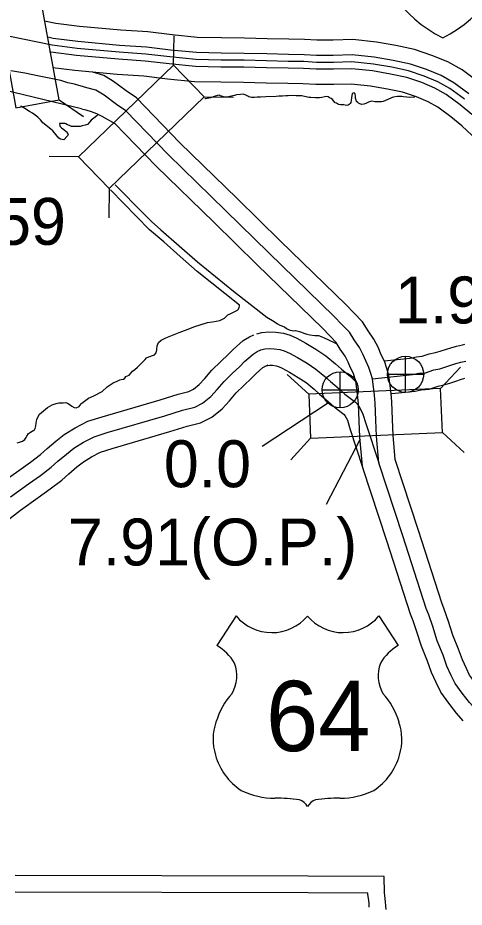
# Model space of a CAD drawing. Extents: x -83719 to 153526, y -11835 to 11446.
# Drawn here: x -2255.2 to -2121.1, y 1185.3 to 1452.3 of the extents above; entities that cross this region are included whole.
import ezdxf

# ---------------------------------------------------------------- set-up
doc = ezdxf.new("R2010")
doc.units = 0
for name, color, linetype in [('Level 10', 7, 'Continuous'), ('Level 15', 7, 'Continuous'), ('Level 19', 7, 'Continuous'), ('Level 20', 7, 'Continuous'), ('Level 22', 7, 'Continuous'), ('Level 23', 7, 'Continuous'), ('Level 25', 7, 'Continuous'), ('Level 26', 7, 'Continuous'), ('Level 58', 7, 'Continuous'), ('Level 59', 7, 'Continuous'), ('Level 9', 7, 'Continuous')]:
    doc.layers.add(name, color=color, linetype=linetype)

msp = doc.modelspace()

# ---------------------------------------------------------------- linework, layer by layer
at = {"layer": 'Level 10'}
for points in [[(-2260.36, 1312.57), (-2254.83, 1316.47), (-2251.37, 1318.93), (-2248.36, 1321.25), (-2246.38, 1323.01), (-2243.74, 1325.25), (-2241.2, 1327.26), (-2237.91, 1329.27), (-2234.14, 1331.2), (-2229.78, 1332.57), (-2212.46, 1337.66), (-2207.05, 1339.38), (-2203.77, 1340.18), (-2202.41, 1340.86), (-2200.68, 1342.29), (-2199.05, 1344.03), (-2196.88, 1346.6), (-2194.25, 1349.13), (-2192.05, 1351.21), (-2190.55, 1352.77), (-2187.46, 1355.48), (-2185.61, 1356.55), (-2184.34, 1357.15)], [(-2183.39, 1357.49), (-2181.85, 1357.87), (-2179.78, 1358.05), (-2177.73, 1357.99), (-2175.36, 1357.61), (-2173.42, 1357.01), (-2171.42, 1356.13), (-2168.7, 1354.66), (-2165.64, 1352.85), (-2162.68, 1350.85), (-2159.74, 1348.48), (-2157.98, 1346.9), (-2155.29, 1344.63), (-2153.74, 1343.15), (-2153.72, 1343.14)], [(-2145.14, 1349.35), (-2137.37, 1350.18), (-2135.46, 1350.55), (-2133.79, 1350.72), (-2131.61, 1351.44), (-2129.71, 1351.85), (-2128.4, 1352.23), (-2126.43, 1352.89), (-2125.11, 1353.3), (-2123.42, 1353.78), (-2121.67, 1354.19), (-2120.91, 1354.34)], [(-2258.87, 1301.02), (-2254.38, 1304.55), (-2249.05, 1308.3), (-2245.41, 1310.9), (-2241.97, 1313.55), (-2239.82, 1315.46), (-2237.4, 1317.51), (-2235.47, 1319.04), (-2233.02, 1320.54), (-2230.33, 1321.91), (-2226.87, 1323), (-2209.53, 1328.09), (-2204.34, 1329.75), (-2200.33, 1330.73), (-2196.94, 1332.41), (-2193.81, 1334.99), (-2191.57, 1337.38), (-2189.57, 1339.76), (-2187.34, 1341.9), (-2185.02, 1344.1), (-2183.64, 1345.53), (-2181.61, 1347.31), (-2180.96, 1347.68), (-2180.04, 1348.12)], [(-2181, 1347.78), (-2180.21, 1347.97), (-2179.49, 1348.04), (-2178.68, 1348.01), (-2177.64, 1347.84), (-2176.91, 1347.62), (-2175.82, 1347.14), (-2173.63, 1345.96), (-2170.98, 1344.39), (-2168.63, 1342.81), (-2166.23, 1340.86), (-2164.54, 1339.36), (-2161.97, 1337.18), (-2160.21, 1335.51), (-2157.19, 1333.23), (-2156.95, 1332.97), (-2156.22, 1331.5), (-2155.47, 1328.99), (-2151.53, 1317.16)], [(-2142.87, 1339.53), (-2135.89, 1340.28), (-2134.02, 1340.65), (-2131.7, 1340.88), (-2128.98, 1341.78), (-2127.23, 1342.16), (-2125.42, 1342.69), (-2123.36, 1343.37), (-2122.23, 1343.73), (-2120.93, 1344.1)], [(-2144.54, 1184.64), (-2144.67, 1185.72), (-2144.72, 1186.96), (-2144.96, 1188.82), (-2145.09, 1189.59), (-2145.17, 1194.54), (-2167.98, 1194.68), (-2255.99, 1194.88)]]:
    msp.add_lwpolyline(points, dxfattribs=at)
at = {"layer": 'Level 15'}
for points in [[(-2236.07, 1425.02), (-2409.06, 1466.86)], [(-2229.34, 1435.04), (-2232.67, 1435.99)], [(-2143.78, 1344.93), (-2144.37, 1347.02), (-2145.1, 1349.25), (-2146.12, 1351.4), (-2146.92, 1353.27), (-2148.28, 1355.9), (-2150, 1358.37), (-2151.64, 1361.02), (-2154.27, 1363.77), (-2156.61, 1366.2), (-2176.31, 1385.31), (-2189.27, 1398.08), (-2206.51, 1414.84), (-2219.51, 1428.3), (-2222.58, 1430.39), (-2226.41, 1433.23), (-2229.34, 1435.04)], [(-2236.07, 1425.02), (-2234.78, 1424.66), (-2233.1, 1424.19), (-2231.49, 1423.59), (-2229.88, 1422.79), (-2225.99, 1420.61)], [(-2153.5, 1342.58), (-2153.94, 1344.11), (-2154.4, 1345.53), (-2155.24, 1347.29), (-2155.97, 1349), (-2156.87, 1350.73), (-2158.36, 1352.88), (-2159.58, 1354.86), (-2161.49, 1356.84), (-2163.7, 1359.14), (-2183.3, 1378.16), (-2196.26, 1390.94), (-2213.59, 1407.78), (-2225.99, 1420.61)], [(-2151.72, 1317.73), (-2152.44, 1326.42), (-2152.65, 1331.32), (-2152.87, 1336.35), (-2153.05, 1338.48), (-2153.65, 1343.32)], [(-2141.85, 1319.74), (-2142.46, 1327.05), (-2142.66, 1331.75), (-2142.88, 1337), (-2143.11, 1339.53), (-2143.78, 1344.93)], [(-2113.97, 1247.95), (-2115.75, 1249.95), (-2117.78, 1252.6), (-2119.56, 1255.03), (-2120.5, 1256.98), (-2121.67, 1259.55), (-2122.83, 1262.79), (-2124.58, 1267.01), (-2125.81, 1271.12), (-2127.11, 1274.84), (-2127.88, 1276.73), (-2134.84, 1298.38), (-2141.85, 1319.74)], [(-2121.44, 1241.31), (-2123.46, 1243.58), (-2125.78, 1246.6), (-2128.16, 1249.85), (-2129.56, 1252.73), (-2130.95, 1255.79), (-2132.16, 1259.19), (-2134.01, 1263.65), (-2135.32, 1268.04), (-2136.46, 1271.29), (-2137.29, 1273.31), (-2144.35, 1295.29), (-2151.53, 1317.18)]]:
    msp.add_lwpolyline(points, dxfattribs=at)
at = {"layer": 'Level 19'}
for points in [[(-2116.98, 1433.15), (-2121.78, 1436.68), (-2126.09, 1439.13), (-2130.83, 1441.07), (-2136.08, 1442.85), (-2141.64, 1444.05), (-2147.5, 1445.06), (-2154.6, 1445.79), (-2160.49, 1445.62), (-2165.34, 1445.64), (-2169.05, 1445.84), (-2173.83, 1445.93), (-2180.29, 1446.06), (-2187.13, 1446.25), (-2194.03, 1446.3), (-2201.26, 1446.47), (-2208.81, 1447.22), (-2216.09, 1448.08), (-2224.24, 1448.62), (-2236.61, 1449.77), (-2243.75, 1450.67), (-2247.16, 1451.37)], [(-2119.79, 1429.53), (-2124.28, 1432.83), (-2128.1, 1435), (-2132.44, 1436.78), (-2137.3, 1438.43), (-2142.51, 1439.55), (-2148.13, 1440.51), (-2154.77, 1441.2), (-2160.43, 1441.04), (-2165.47, 1441.05), (-2169.22, 1441.26), (-2173.92, 1441.35), (-2180.4, 1441.48), (-2187.21, 1441.67), (-2194.1, 1441.72), (-2201.54, 1441.9), (-2209.31, 1442.66), (-2216.51, 1443.51), (-2224.6, 1444.05), (-2237.11, 1445.21), (-2244.5, 1446.14), (-2246.16, 1446.48)], [(-2118.81, 1423.34), (-2122.35, 1426.23), (-2126.56, 1429.33), (-2129.93, 1431.25), (-2133.9, 1432.87), (-2138.41, 1434.41), (-2143.3, 1435.46), (-2148.69, 1436.38), (-2154.92, 1437.02), (-2160.38, 1436.87), (-2165.59, 1436.89), (-2169.37, 1437.09), (-2174, 1437.18), (-2180.5, 1437.31), (-2187.28, 1437.5), (-2194.17, 1437.55), (-2201.79, 1437.73), (-2209.76, 1438.52), (-2216.9, 1439.36), (-2224.93, 1439.9), (-2237.56, 1441.07), (-2245.19, 1442.03), (-2245.49, 1442.09)], [(-2118.77, 1416.98), (-2121.84, 1419.9), (-2125.16, 1422.61), (-2129.05, 1425.48), (-2131.94, 1427.12), (-2135.51, 1428.58), (-2139.64, 1429.98), (-2144.17, 1430.96), (-2149.32, 1431.84), (-2155.09, 1432.43), (-2160.32, 1432.29), (-2165.72, 1432.3), (-2169.54, 1432.51), (-2174.09, 1432.6), (-2180.61, 1432.73), (-2187.36, 1432.92), (-2194.24, 1432.97), (-2202.07, 1433.16), (-2210.25, 1433.96), (-2217.32, 1434.8), (-2225.3, 1435.33), (-2238.06, 1436.51), (-2244.68, 1437.34)]]:
    msp.add_lwpolyline(points, dxfattribs=at)
at = {"layer": 'Level 20'}
for p, q in [((-2208.41, 1438.11), (-2208.26, 1446.91)), ((-2199.24, 1428.62), (-2190.44, 1428.47)), ((-2242.72, 1427.73), (-2235.48, 1422.72)), ((-2236.89, 1410.59), (-2245.69, 1410.74)), ((-2227.72, 1401.1), (-2227.87, 1392.3)), ((-2128.24, 1341), (-2122.29, 1347.48)), ((-2167.8, 1339.33), (-2174.28, 1345.28)), ((-2127.68, 1327.81), (-2121.2, 1321.86)), ((-2167.25, 1326.14), (-2173.2, 1319.66))]:
    msp.add_line(p, q, dxfattribs=at)
for points in [[(-2242.72, 1427.73), (-2249.82, 1466.69), (-2262.81, 1464.32), (-2255.71, 1425.36)], [(-2208.41, 1438.11), (-2236.89, 1410.59), (-2227.72, 1401.1), (-2199.24, 1428.62)], [(-2128.24, 1341), (-2167.8, 1339.33), (-2167.25, 1326.14), (-2127.68, 1327.81)]]:
    msp.add_lwpolyline(points, close=True, dxfattribs=at)
at = {"layer": 'Level 22'}
for p, q in [((-2189.63, 1272.76), (-2195.4, 1263.84)), ((-2146.74, 1272.76), (-2140.97, 1263.84))]:
    msp.add_line(p, q, dxfattribs=at)
for centre, radius, start, end in [((-2178.89, 1281.8), 14.04, 220.075, 319.6701), ((-2157.48, 1281.8), 14.04, 220.3299, 319.925), ((-2202.94, 1250.89), 14.99, 30.7809, 59.9883), ((-2133.43, 1250.89), 14.99, 120.0117, 149.2191), ((-2199.64, 1254.84), 10.28, 328.8105, 21.2108), ((-2136.73, 1254.84), 10.28, 158.7892, 211.1895), ((-2172.77, 1233.78), 23.97, 138.9565, 162.6913), ((-2163.6, 1233.78), 23.97, 17.3087, 41.0435), ((-2180.69, 1235.74), 15.84, 160.9576, 197.3819), ((-2155.69, 1235.74), 15.84, 342.6181, 19.0424), ((-2178.11, 1235.79), 18.33, 195.1074, 237.1312), ((-2158.26, 1235.79), 18.33, 302.8688, 344.8926), ((-2177.77, 1241.56), 23.53, 244.0771, 269.5779), ((-2158.6, 1241.56), 23.53, 270.4221, 295.9229), ((-2177.22, 1174.92), 43.11, 81.1942, 90.9539), ((-2159.15, 1174.92), 43.11, 89.0461, 98.8058), ((-2171.83, 1213.57), 4.13, 28.0342, 72.9864), ((-2164.54, 1213.57), 4.13, 107.0136, 151.9658)]:
    msp.add_arc(centre, radius, start, end, dxfattribs=at)
at = {"layer": 'Level 23'}
for centre, start, end in [((-2109.59, 1482.39), 186.3923, 243.4571), ((-2145.6, 1482.39), 296.5429, 353.6077)]:
    msp.add_arc(centre, 40.29, start, end, dxfattribs=at)
at = {"layer": 'Level 25'}
msp.add_line((-2181.77, 1323.78), (-2162.19, 1336.66), dxfattribs=at)
at = {"layer": 'Level 26'}
for p, q in [((-2138.73, 1339.89), (-2138.73, 1350.72)), ((-2158.37, 1335.26), (-2158.37, 1346.1)), ((-2144.14, 1345.3), (-2133.31, 1345.3)), ((-2163.79, 1340.68), (-2152.95, 1340.68))]:
    msp.add_line(p, q, dxfattribs=at)
for centre in [(-2138.73, 1345.3), (-2158.37, 1340.68)]:
    msp.add_circle(centre, 5.42, dxfattribs=at)
at = {"layer": 'Level 58'}
msp.add_line((-2152.4, 1325.8), (-2162.59, 1306.22), dxfattribs=at)
at = {"layer": 'Level 59'}
for points in [[(-2121.07, 1427.88), (-2125.42, 1431.08), (-2129.01, 1433.12), (-2133.17, 1434.83), (-2137.86, 1436.42), (-2142.9, 1437.5), (-2148.41, 1438.45), (-2154.85, 1439.11), (-2160.4, 1438.95), (-2165.53, 1438.97), (-2169.29, 1439.18), (-2173.96, 1439.27), (-2180.45, 1439.39), (-2187.24, 1439.58), (-2194.14, 1439.64), (-2201.66, 1439.82), (-2209.53, 1440.59), (-2216.7, 1441.44), (-2224.77, 1441.98), (-2237.34, 1443.14), (-2244.84, 1444.08), (-2257.57, 1446.71)], [(-2148.69, 1343.94), (-2149.15, 1345.56), (-2149.75, 1347.39), (-2150.68, 1349.34), (-2151.44, 1351.13), (-2152.58, 1353.32), (-2154.18, 1355.63), (-2155.61, 1357.94), (-2157.88, 1360.3), (-2160.15, 1362.67), (-2179.81, 1381.74), (-2192.77, 1394.51), (-2210.05, 1411.31), (-2222.75, 1424.45), (-2225.48, 1426.31), (-2229.22, 1429.09), (-2231.74, 1430.65), (-2234.41, 1431.27), (-2238.09, 1432.41), (-2240.13, 1432.81), (-2242.24, 1433.51), (-2248.79, 1434.84), (-2253, 1435.67), (-2257.24, 1436.44)], [(-2257.37, 1308.56), (-2251.94, 1312.39), (-2248.39, 1314.91), (-2245.17, 1317.4), (-2243.1, 1319.24), (-2240.57, 1321.38), (-2238.34, 1323.15), (-2235.47, 1324.9), (-2232.23, 1326.56), (-2228.32, 1327.79), (-2211, 1332.88), (-2205.7, 1334.56), (-2202.05, 1335.46), (-2199.67, 1336.63), (-2197.24, 1338.64), (-2195.31, 1340.71), (-2193.22, 1343.18), (-2190.8, 1345.52), (-2188.54, 1347.66), (-2187.1, 1349.15), (-2184.54, 1351.39), (-2183.28, 1352.12), (-2182.19, 1352.63)], [(-2182.19, 1352.63), (-2181.03, 1352.92), (-2179.64, 1353.04), (-2178.2, 1353), (-2176.5, 1352.73), (-2175.16, 1352.31), (-2173.62, 1351.64), (-2171.17, 1350.31), (-2168.31, 1348.62), (-2165.65, 1346.83), (-2162.99, 1344.67), (-2161.26, 1343.13), (-2158.63, 1340.9), (-2156.97, 1339.33), (-2153.81, 1336.94), (-2152.79, 1335.83), (-2151.55, 1333.34), (-2150.7, 1330.49), (-2146.78, 1318.74)], [(-2148.69, 1343.94), (-2136.63, 1345.23), (-2134.74, 1345.6), (-2132.74, 1345.8), (-2130.29, 1346.61), (-2128.47, 1347), (-2126.91, 1347.46), (-2124.89, 1348.13), (-2123.67, 1348.52), (-2122.18, 1348.94), (-2120.62, 1349.3)], [(-2146.78, 1318.74), (-2147.45, 1326.74), (-2147.66, 1331.54), (-2147.87, 1336.67), (-2148.08, 1339.01), (-2148.69, 1343.94)], [(-2117.7, 1244.63), (-2119.6, 1246.77), (-2121.78, 1249.6), (-2123.86, 1252.44), (-2125.03, 1254.85), (-2126.31, 1257.67), (-2127.49, 1260.99), (-2129.3, 1265.33), (-2130.56, 1269.58), (-2131.79, 1273.06), (-2132.58, 1275.02), (-2139.6, 1296.83), (-2146.78, 1318.74)], [(-2149.66, 1185.31), (-2149.71, 1186.54), (-2149.9, 1188.07), (-2150.09, 1189.1), (-2150.09, 1189.57), (-2168.01, 1189.68), (-2255.96, 1189.88)]]:
    msp.add_lwpolyline(points, dxfattribs=at)
at = {"layer": 'Level 9'}
for points in [[(-2189.47, 1429.17), (-2190.07, 1428.99), (-2191.53, 1428.67), (-2192.26, 1428.52), (-2193.09, 1428.51), (-2194.33, 1428.92), (-2194.66, 1429.08), (-2195.16, 1429.04), (-2196.22, 1428.69), (-2197.35, 1428.27), (-2198.28, 1428.12), (-2198.81, 1428.05), (-2198.99, 1428.04)], [(-2135.94, 1428.53), (-2136.23, 1428.47), (-2137.66, 1428.44), (-2138.36, 1428.47), (-2139.33, 1428.62), (-2139.83, 1428.68), (-2141.16, 1428.69), (-2142.42, 1428.5), (-2145.5, 1427.22), (-2145.99, 1427.14), (-2146.73, 1427.13), (-2147.43, 1427.15), (-2147.93, 1427.14), (-2148.83, 1427.33), (-2149.29, 1427.22), (-2149.89, 1426.98), (-2150.65, 1426.63), (-2151.31, 1426.39), (-2151.91, 1426.34), (-2152.51, 1426.5), (-2152.85, 1426.73), (-2153.11, 1426.92), (-2153.45, 1427.25), (-2153.62, 1427.58), (-2153.8, 1428.21), (-2153.81, 1428.75), (-2153.89, 1429.48), (-2154.06, 1429.68), (-2154.19, 1429.78), (-2154.46, 1429.74), (-2154.79, 1429.47), (-2154.85, 1429), (-2154.94, 1428.33), (-2155.06, 1427.56), (-2155.18, 1426.89), (-2155.37, 1426.59), (-2155.64, 1426.35), (-2155.96, 1426.08), (-2156.43, 1426), (-2157.23, 1426.19), (-2158.26, 1426.21), (-2158.83, 1426.36), (-2159.5, 1426.69), (-2159.9, 1426.78), (-2160.31, 1427.27), (-2160.69, 1427.77), (-2161.12, 1428.1), (-2161.63, 1428.35), (-2162, 1428.65), (-2162.47, 1428.74), (-2162.96, 1428.63), (-2163.86, 1428.42), (-2164.62, 1428.34), (-2165.76, 1428.35), (-2167.22, 1428.43), (-2167.82, 1428.45), (-2169.93, 1428.89), (-2171.62, 1428.96), (-2172.82, 1428.97), (-2173.99, 1428.92), (-2174.65, 1428.91), (-2175.72, 1428.86), (-2176.78, 1428.77), (-2177.58, 1428.73), (-2180.71, 1428.64), (-2182.34, 1428.52), (-2183.27, 1428.47), (-2184.13, 1428.45), (-2184.96, 1428.44), (-2185.83, 1428.59), (-2186.14, 1428.79), (-2186.51, 1429.02), (-2186.88, 1429.24), (-2187.54, 1429.43), (-2188.31, 1429.32), (-2189.47, 1429.17)], [(-2233.12, 1421.65), (-2233.51, 1421.11), (-2234.2, 1420.33), (-2234.96, 1420.08), (-2235.79, 1419.9), (-2236.39, 1419.69), (-2237.15, 1419.68), (-2237.95, 1419.74), (-2238.99, 1419.75), (-2239.62, 1420.04), (-2240.23, 1420.23), (-2240.73, 1420.49), (-2240.93, 1420.62), (-2241.23, 1420.65), (-2241.63, 1420.64), (-2241.9, 1420.64), (-2242.26, 1420.63), (-2242.66, 1420.56), (-2242.55, 1419.99), (-2242.45, 1419.73), (-2242.01, 1419.27), (-2241.37, 1418.81), (-2240.59, 1418.22), (-2240.39, 1418.06), (-2240.38, 1417.76), (-2240.11, 1417.5), (-2240.08, 1417.26), (-2240.11, 1417.03), (-2240.34, 1416.79), (-2241.32, 1415.74), (-2242.29, 1415.93), (-2242.82, 1416.25), (-2244.62, 1418.36), (-2246.27, 1419.67), (-2247.63, 1420.81), (-2248.34, 1421.67), (-2249.18, 1422.49), (-2250.73, 1423.66), (-2251.64, 1424.22), (-2253.05, 1425.06), (-2254.06, 1425.68), (-2254.26, 1425.78)], [(-2231.09, 1423.22), (-2231.41, 1422.88), (-2232.33, 1422.2), (-2233.12, 1421.65)], [(-2225.93, 1402.24), (-2217.32, 1393.44), (-2214.98, 1391.21), (-2212.21, 1388.69), (-2201.23, 1379.05)], [(-2254.61, 1324.96), (-2253.75, 1325.27), (-2253.06, 1325.78), (-2252.67, 1326.32), (-2252.44, 1326.73), (-2251.92, 1327.54), (-2251.36, 1327.95), (-2250.31, 1328.53), (-2250.18, 1328.63), (-2249.95, 1329.07), (-2249.76, 1329.84), (-2249.64, 1330.68), (-2249.46, 1331.81), (-2248.62, 1333.33), (-2246.19, 1335.31), (-2244.87, 1336.16), (-2243.62, 1336.58), (-2242.82, 1336.7), (-2241.52, 1336.78), (-2240.76, 1336.8), (-2240.22, 1336.6), (-2239.48, 1336.15), (-2238.97, 1335.72), (-2238.24, 1335.3), (-2237.63, 1335.24), (-2236.78, 1335.66), (-2236.09, 1336.47), (-2235.89, 1336.61), (-2233.89, 1338.14), (-2232.37, 1338.87), (-2229.83, 1340.18), (-2228.35, 1341.54), (-2226.54, 1342.7), (-2225.28, 1343.25), (-2224.56, 1343.6), (-2224.09, 1343.74), (-2223.46, 1343.89), (-2223.03, 1344.16), (-2222.71, 1344.6), (-2221.68, 1345.08), (-2220.74, 1346.23), (-2219.98, 1346.78), (-2219.19, 1347.43), (-2218.08, 1348.51), (-2217.75, 1348.92), (-2216.93, 1349.73), (-2216.47, 1350.21), (-2215.81, 1350.52), (-2214.39, 1351.04), (-2214.13, 1351.18), (-2213.64, 1351.72), (-2213.45, 1352.62), (-2213.46, 1352.89), (-2213.3, 1353.83), (-2212.95, 1354.84), (-2212.13, 1355.55), (-2210.71, 1356.21), (-2208.2, 1357.22), (-2206.71, 1357.84), (-2204.36, 1358.78), (-2202.05, 1359.69), (-2200.43, 1360.21), (-2198.24, 1360.82), (-2196.74, 1361.07), (-2195.65, 1361.26), (-2194.55, 1361.48), (-2193.73, 1361.82), (-2193.13, 1362.2), (-2192.68, 1362.61), (-2192.08, 1363.12), (-2191.36, 1363.5), (-2190.43, 1363.98), (-2189.64, 1364.33), (-2189.15, 1364.6), (-2188.88, 1364.91), (-2188.79, 1365.21), (-2188.69, 1365.41), (-2188.57, 1365.81), (-2188.57, 1366.08), (-2201.32, 1376.22), (-2206.45, 1380.64), (-2211.35, 1385.06), (-2215.57, 1388.66), (-2223.39, 1396.68), (-2227.31, 1400.72)], [(-2201.23, 1379.05), (-2190.4, 1370.29), (-2180.42, 1362.51), (-2178.2, 1361.14), (-2177.16, 1360.49), (-2176.45, 1360.04), (-2175.08, 1359.52), (-2174.47, 1359.1), (-2173.67, 1358.68), (-2172.43, 1358.4), (-2171.77, 1358.41), (-2170.3, 1358.07), (-2169.02, 1357.59), (-2168.42, 1357.33), (-2167.45, 1357.15), (-2166.02, 1356.97), (-2164.92, 1356.95), (-2164.12, 1356.7), (-2163.18, 1356.25), (-2162.07, 1355.73), (-2159.82, 1354.67), (-2159.58, 1354.58)], [(-2255.37, 1324.78), (-2254.61, 1324.96)]]:
    msp.add_lwpolyline(points, dxfattribs=at)

# ---------------------------------------------------------------- texts
at = {"layer": 'Level 22'}
msp.add_text('64', height=21.12, dxfattribs=at).set_placement((-2180.66, 1232.17))
at = {"layer": 'Level 25'}
for s, p in [('1.90', (-2141.92, 1360.59)), ('0.0', (-2211.31, 1311.41))]:
    msp.add_text(s, height=14.08, dxfattribs=at).set_placement(p)
at = {"layer": 'Level 58'}
for s, p in [('6.59', (-2277.37, 1384.19)), ('7.91(O.P.)', (-2240.11, 1287.92))]:
    msp.add_text(s, height=14.08, dxfattribs=at).set_placement(p)

doc.saveas('drawing.dxf')
